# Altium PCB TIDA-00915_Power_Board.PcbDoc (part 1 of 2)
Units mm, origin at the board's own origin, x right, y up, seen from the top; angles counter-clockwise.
Board outline 80 x 46 mm, 3 copper layers (Top Layer, Signal Layer 1, Base Aluminium), stack 1.964 mm thick; 95 components, 53 nets, 450 pads, 406 vias.
Unrouted connection lines stored in the file: 2.
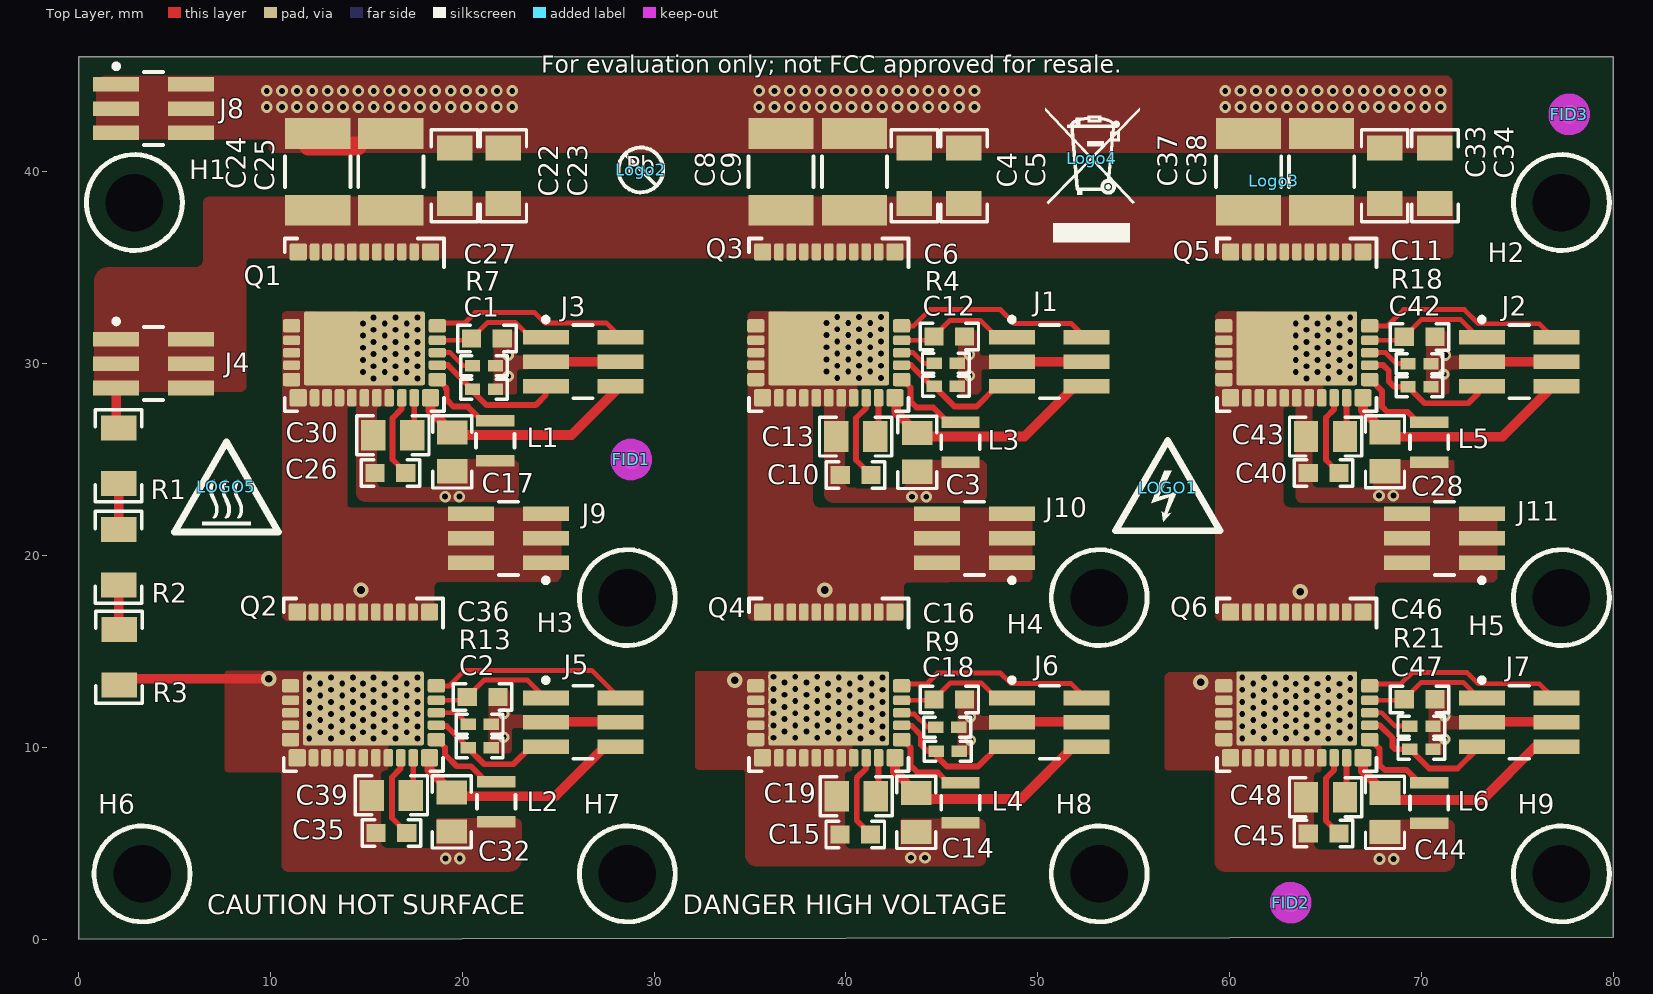
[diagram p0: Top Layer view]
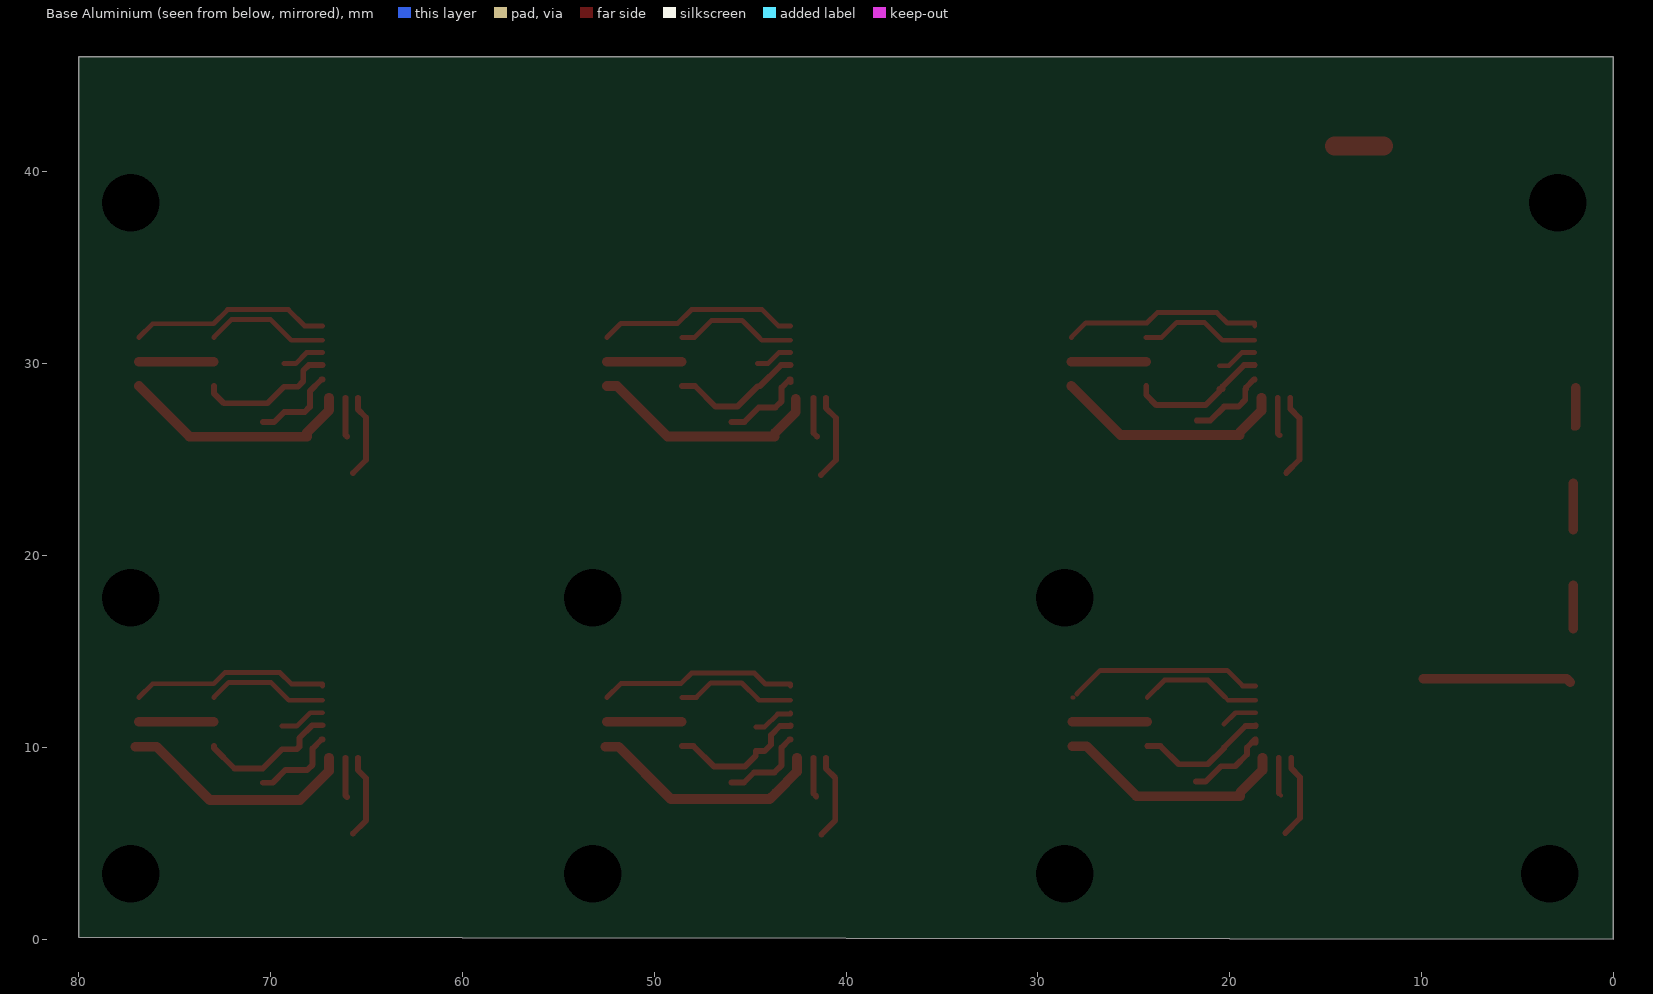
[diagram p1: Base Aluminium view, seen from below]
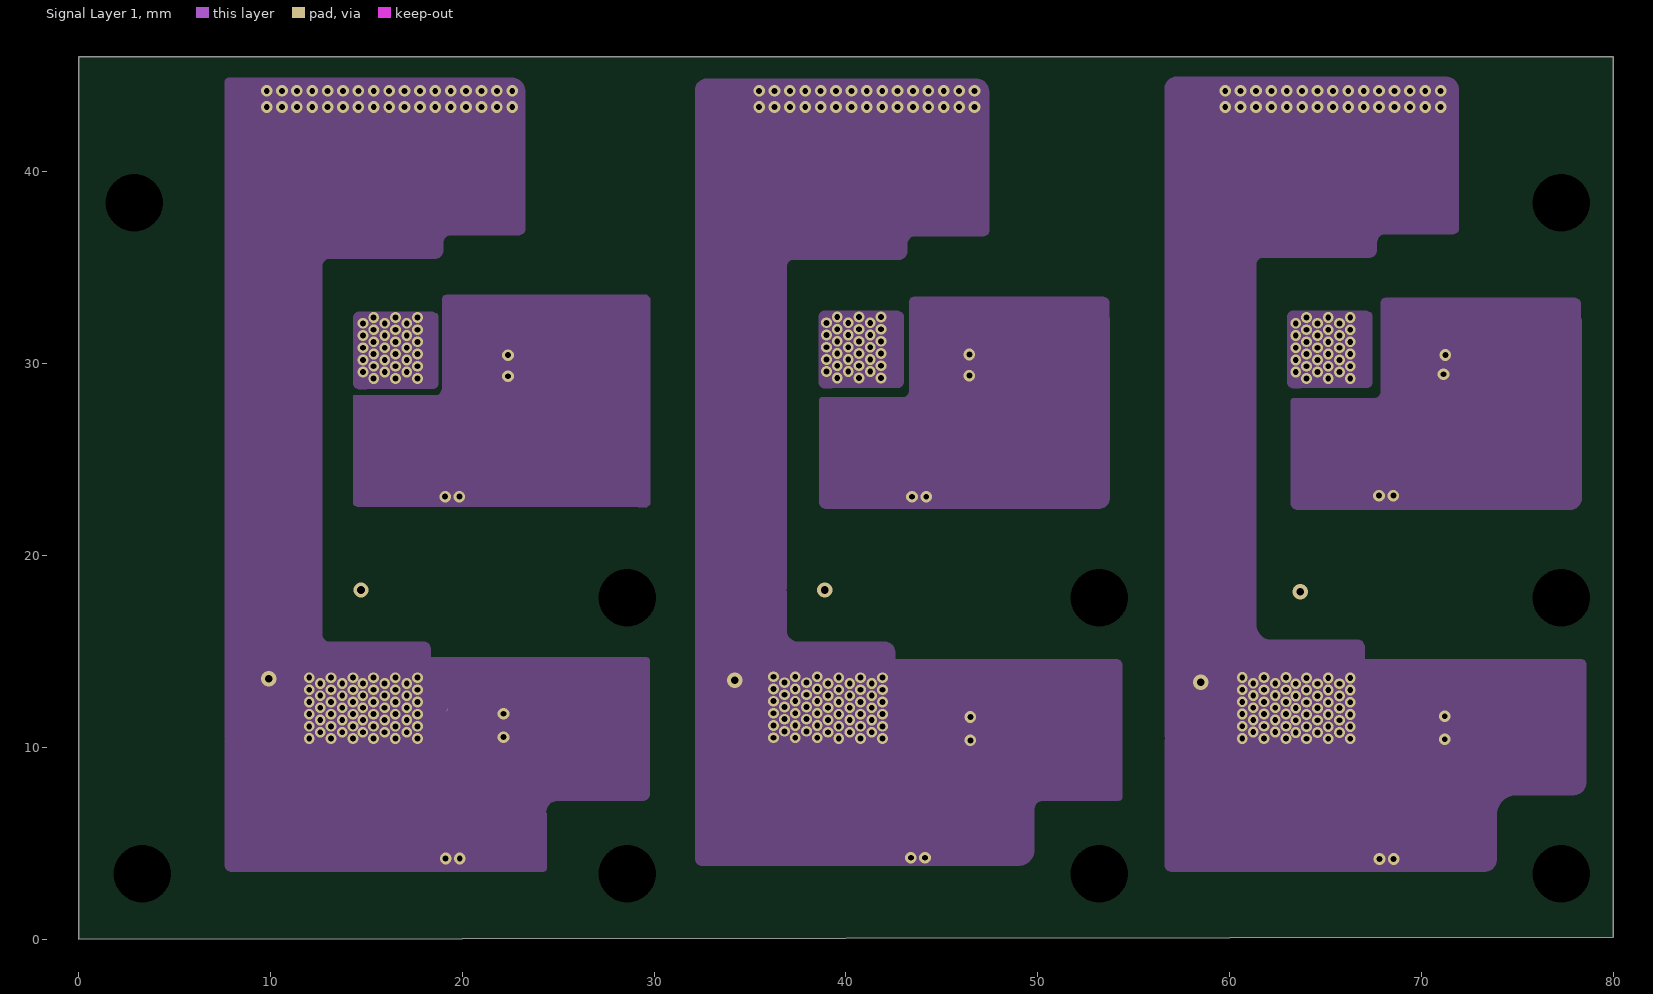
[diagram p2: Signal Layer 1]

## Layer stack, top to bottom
Top Solder: solder mask 0.0102, Solder Resist, Dk 3.5
Top Layer: signal copper 0.07
Dielectric1: dielectric 0.152, Dielectric, Dk 3.4
Signal Layer 1: signal copper 0.07
Dielectric 2: dielectric 0.152, Dk 3.4
Base Aluminium: signal copper 1.52

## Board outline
0,0 80,0.1 80,46 0,46

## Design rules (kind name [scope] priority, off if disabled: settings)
AcuteAngle [All] p1: minimum=4.50000000000000E+0001 checktracksonly=FALSE
AssemblyTestPointUsage [All] p1: valid=2
BoardOutlineClearance BoardOutlineClearance_MountingHoles [OnCopper and InComponentClass('Mounting Holes')] p1: gap=1.016 ignorepadtopadclearanceinfootprint=FALSE
BoardOutlineClearance BoardOutlineClearance_Poly [OnCopper and IsPoly] p2: gap=0.635 ignorepadtopadclearanceinfootprint=FALSE
BoardOutlineClearance [OnCopper and Not InComponentClass('Logo') and not InComponentClass('FiducialMark') and not InRegion(1000,500,4000,800) and not InPoly] p3: gap=0.5 ignorepadtopadclearanceinfootprint=FALSE
Clearance "PhaseU Sw Node" [InNetClass('PhaseU') vs NOT InNetClass('PhaseU')] p1: gap=1.6 ignorepadtopadclearanceinfootprint=TRUE
Clearance "PhaseV Sw Node" [InNetClass('PhaseV') vs NOT InNetClass('PhaseV')] p2: gap=1.6 ignorepadtopadclearanceinfootprint=FALSE
Clearance "PhaseW Sw Node" [InNetClass('PhaseW') vs NOT InNetClass('PhaseW')] p3: gap=1.6 ignorepadtopadclearanceinfootprint=FALSE except(1.524: Arc-Arc Arc-Track Track-Track)
Clearance Clearance_Keepouts [((IsTrack Or IsArc) And Not InPoly) And IsFree and IsKeepOut vs ((IsTrack Or IsArc) And Not InPoly) And IsFree and IsKeepOut] p4: gap=0 ignorepadtopadclearanceinfootprint=FALSE
Clearance Clearance_Poly [InPolygon] p5: gap=0.635 ignorepadtopadclearanceinfootprint=FALSE except(0: Arc-Hole Track-Hole SMDPad-Hole THPad-Hole Via-Hole Fill-Hole Poly-Hole Region-Hole Text-Hole; 0.254: Arc-Fill Arc-Poly Arc-Region Track-Fill Track-Poly Track-Region SMDPad-Fill SMDPad-Poly SMDPad-Region THPad-Fill THPad-Poly THPad-Region Via-Fill Via-Poly Via-Region Fill-Fill Fill-Poly Fill-Region Poly-Poly Poly-Region Region-Region)
Clearance Clearance_FiducialMark [IsKeepOut and InComponentClass('FiducialMark') vs IsPad and InComponentClass('FiducialMark')] p6: gap=0 ignorepadtopadclearanceinfootprint=FALSE
Clearance [All] p7: gap=0.254 ignorepadtopadclearanceinfootprint=TRUE except(0.203: Arc-SMDPad Track-SMDPad)
ComponentClearance ComponentClearance_MountingHoles_FiducialMarks [InComponentClass('Mounting Holes') vs InComponentClass('FiducialMark')] p1: gap=1.27 collisioncheckmode=3 verticalgap=0.254 showdistances=FALSE
ComponentClearance ComponentClearance_Shunt [InComponentClass('Header') vs InComponentClass('Shunt')] p2: gap=0 collisioncheckmode=3 verticalgap=0 showdistances=FALSE
ComponentClearance ComponentClearance_Logo [InComponentClass('Logo')] p3: gap=1.27 collisioncheckmode=3 verticalgap=0.254 showdistances=FALSE
ComponentClearance ComponentClearance_ScrewToNut [(HasFootprint('NY PMS 440 0025 PH')) vs (HasFootprint('Keystone_1902C'))] p4: gap=0.127 collisioncheckmode=3 verticalgap=0.254 showdistances=FALSE
ComponentClearance ComponentClearance_MountingHoles [InComponentClass('Mounting Holes')] p5: gap=6.35 collisioncheckmode=3 verticalgap=2540 showdistances=FALSE
ComponentClearance ComponentClearance_SmallPassives [HasFootprint('0201*') or HasFootprint('0402*') or HasFootprint('0508') or HasFootprint('0603*') or HasFootprint('0612') or HasFootprint('0805*') or HasFootprint('0815*') or HasFootprint('0830*') or HasFootprint('1206*') or HasFootprint('1210*') or HasFootprint('1808*') or HasFootprint('1812*') or HasFootprint('1825*') or HasFootprint('2010*') or HasFootprint('2220*') or HasFootprint('2225*') or HasFootprint('2512*') or HasFootprint('2728*') or HasFootprint('3518*') vs HasFootprint('0201*') or HasFootprint('0402*') or HasFootprint('0508') or HasFootprint('0603*') or HasFootprint('0612') or HasFootprint('0805*') or HasFootprint('0815*') or HasFootprint('0830*') or HasFootprint('1206*') or HasFootprint('1210*') or HasFootprint('1808*') or HasFootprint('1812*') or HasFootprint('1825*') or HasFootprint('2010*') or HasFootprint('2220*') or HasFootprint('2225*') or HasFootprint('2512*') or HasFootprint('2728*') or HasFootprint('3518*')] p6: gap=0.38 collisioncheckmode=3 verticalgap=0.254 showdistances=FALSE
ComponentClearance ComponentClearance_THtoSMT [IsThruComponent vs IsSMTComponent] p7: gap=0.5 collisioncheckmode=3 verticalgap=0.762 showdistances=FALSE
ComponentClearance ComponentClearance_THtoTH [IsThruComponent vs IsThruComponent] p8: gap=0.762 collisioncheckmode=3 verticalgap=0.762 showdistances=FALSE
ComponentClearance [All] p9: gap=0.381 collisioncheckmode=3 verticalgap=0.254 showdistances=FALSE
DiffPairsRouting [All] p1: maxlimit=2.54 minlimit=0.254 mostfreqgap=0.254 toplayer_minwidth=0.381 toplayer_maxwidth=0.381 toplayer_prefwidth=0.381 midlayer1_minwidth=0.381 midlayer1_maxwidth=0.381 midlayer1_prefwidth=0.381 bottomlayer_minwidth=0.381 bottomlayer_maxwidth=0.381 bottomlayer_prefwidth=0.381 maxuncoupledlength=25.4
FabricationTestPointUsage TestPointUsage [All] p1: valid=2 allowmultiple=FALSE
FabricationTestpoint Testpoint [All] p1: side=3 testpointundercomponent=TRUE minsize=1.016 maxsize=2.54 preferedsize=1.524 minholesize=0 maxholesize=1.016 preferedholesize=0.813 testpointgrid=0.025 allowsidetop=TRUE allowsidebottom=TRUE usegrid=TRUE gridtolerance=0
FanoutControl Fanout_LCC [IsLCC] p1: bgadir=Out bgaviamode=Centered fanoutstyle=Auto fanoutdirection=Alternating viagrid=0.025 // Fanout_LCC (Default Rule)
FanoutControl Fanout_BGA [IsBGA] p2: bgadir=Out bgaviamode=Centered fanoutstyle=Auto fanoutdirection=Alternating viagrid=0.025 // Fanout_BGA (Default Rule)
FanoutControl Fanout_Default [All] p4: bgadir=Out bgaviamode=Centered fanoutstyle=Auto fanoutdirection=Alternating viagrid=0.025 // Fanout_Default (Default Rule)
FanoutControl Fanout_Small [(CompPinCount < 5)] p5: bgadir=Out bgaviamode=Centered fanoutstyle=Auto fanoutdirection=OutThenIn viagrid=0.025 // Fanout_Small (Default Rule)
HoleSize [All] p1: absolutevalues=TRUE maxlimit=6.375 minlimit=0.2 maxpercent=80.000 minpercent=20.000
MinimumAnnularRing MinimumAnnularRing_ThermalPadVias [IsVia and InAnyComponent] p1: minimumring=0.15
MinimumAnnularRing [All] p2: minimumring=0.203
MinimumSolderMaskSliver MinimumSolderMaskSliver_Logo [InComponentClass('Logo') vs InComponentClass('Logo')] p1: minsoldermaskwidth=0.018
MinimumSolderMaskSliver [All] p2: minsoldermaskwidth=0.1
PlaneConnect [All] p1: planeconnectstyle=Direct reliefexpansion=0.254 reliefentries=4 reliefconductorwidth=0.254 reliefairgap=0.254
PolygonConnect [All] p1: connectstyle=Direct reliefconductorwidth=0.254 reliefentries=4 polygonreliefangle="90 Angle" airgapwidth=0.254
RoutingVias ThermalPadVias [IsVia and InAnyComponent] p1: holewidth=0.2 width=0.5 viastyle="Through Hole" minholewidth=0.2 minwidth=0.5 maxholewidth=0.33 maxwidth=0.6
RoutingVias [All] p2: holewidth=0.406 width=0.864 viastyle="Through Hole" minholewidth=0.2 minwidth=0.508 maxholewidth=1.016 maxwidth=1.651
SilkToBoardRegionClearance [Not ((IsComment or IsDesignator) And (Hide <> 'False')) and not InRegion(1000,500,4000,800)] p1:
SilkToSilkClearance SilkToSilkClearance_Pb-FreeLogo [(HasFootprint('Pb-Free_Overlay_Medium') OR HasFootprint('Pb-Free_Overlay_Small')) vs (HasFootprint('Pb-Free_Overlay_Medium') OR HasFootprint('Pb-Free_Overlay_Small'))] p1: silktosilkclearance=0
SilkToSilkClearance [All] p2: silktosilkclearance=0.102
SilkToSolderMaskClearance SilkToComponentPadClearance [(IsPad or IsFill or IsRegion) and InAnycomponent] p1: minsilkscreentomaskgap=0.127 clearancetoexposedcopper=TRUE
SilkToSolderMaskClearance "Silk to Solder Mask Opening" [All] p2: minsilkscreentomaskgap=0.102 clearancetoexposedcopper=FALSE
SolderMaskExpansion [All] p1: expansion=0.05
Width [All] p1: maxlimit=2.54 minlimit=0.152 preferedwidth=0.254 checkconnectedcopper=TRUE
15 further rules are at their usual default settings.

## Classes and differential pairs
net class PhaseW: 5V_H_W 12V_T_W FAULT_H_W IN_H_W NetC40_1 NetQ5_30 PHASEW SW_H_W VM12V_H_W
net class PhaseV: 5V_H_V 12V_T_V FAULT_H_V IN_H_V NetC10_1 NetQ3_30 PHASEV SW_H_V VM12V_H_V
net class PhaseU: 5V_H_U 12V_T_U FAULT_H_U IN_H_U NetC26_1 NetQ1_30 PHASEU SW_H_U VM12V_H_U
component class Header: J1 J2 J3 J4 J5 J6 J7 J8 J9 J10 J11
component class AssemblyNote: ZZ1
component class FiducialMark: FID1 FID2 FID3
component class EVM_Hardware: FID1 FID2 FID3 H1 H2 H3 H4 H5 H6 H7 H8 H9 LOGO1 Logo2 Logo3 Logo4 LOGO5 ZZ1
component class Phase_U: C1 C2 C17 C22 C23 C24 C25 C26 C27 C30 C32 C35 C36 C39 J3 J4 J5 J8 J9 L1 L2 Q1 Q2 R1 R2 R3 R7 R13
component class Phase_W: C11 C28 C33 C34 C37 C38 C40 C42 C43 C44 C45 C46 C47 C48 J2 J7 J11 L5 L6 Q5 Q6 R18 R21
component class Phase_V: C3 C4 C5 C6 C8 C9 C10 C12 C13 C14 C15 C16 C18 C19 J1 J6 J10 L3 L4 Q3 Q4 R4 R9

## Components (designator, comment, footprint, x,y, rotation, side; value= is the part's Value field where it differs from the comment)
C1 "CGA2B3X7R1E104K050BB" 0402 21.128,28.674 r0 top value=0.1uF
C2 "CGA2B3X7R1E104K050BB" 0402 20.897,9.98 r0 top value=0.1uF
C3 "C2012X7R1V475K125AC" 0805_HV 43.708,25.372 r270 top value=4.7uF
C4 "C1206X103KDRAC7800" 1206 43.565,39.8 r90 top value=0.01uF
C5 "C1206X103KDRAC7800" 1206 46.147,39.8 r90 top value=0.01uF
C6 "06035A181JAT2A" 0603 45.385,31.418 r180 top value=180pF
C8 "C1812V104KDRACTU" 1812_254 36.61,39.996 r90 top value=0.1uF
C9 "C1812V104KDRACTU" 1812_254 40.445,39.996 r90 top value=0.1uF
C10 "GCM188R71E224KA55D" 0603 40.5,24.2 r180 top value=0.22uF
C11 "06035A181JAT2A" 0603 69.9,31.4 r180 top value=180pF
C12 "CGA2B3X7R1E104K050BB" 0402 45.207,28.821 r0 top value=0.1uF
C13 "C2012X7R1V475K125AC" 0805_HV 40.5,26.2 r180 top value=4.7uF
C14 "C2012X7R1V475K125AC" 0805_HV 43.658,6.602 r270 top value=4.7uF
C15 "GCM188R71E224KA55D" 0603 40.483,5.459 r180 top value=0.22uF
C16 "06035A181JAT2A" 0603 45.385,12.495 r180 top value=180pF
C17 "C2012X7R1V475K125AC" 0805_HV 19.477,25.398 r270 top value=4.7uF
C18 "CGA2B3X7R1E104K050BB" 0402 45.309,9.803 r0 top value=0.1uF
C19 "C2012X7R1V475K125AC" 0805_HV 40.533,7.441 r180 top value=4.7uF
C22 "C1206X103KDRAC7800" 1206 19.593,39.8 r90 top value=0.01uF
C23 "C1206X103KDRAC7800" 1206 22.133,39.8 r90 top value=0.01uF
C24 "C1812V104KDRACTU" 1812_254 12.459,39.996 r90 top value=0.1uF
C25 "C1812V104KDRACTU" 1812_254 16.269,39.996 r90 top value=0.1uF
C26 "GCM188R71E224KA55D" 0603 16.251,24.306 r180 top value=0.22uF
C27 "06035A181JAT2A" 0603 21.28,31.316 r180 top value=180pF
C28 "C2012X7R1V475K125AC" 0805_HV 68.1,25.4 r270 top value=4.7uF
C30 "C2012X7R1V475K125AC" 0805_HV 16.378,26.261 r180 top value=4.7uF
C32 "C2012X7R1V475K125AC" 0805_HV 19.45,6.627 r270 top value=4.7uF
C33 "C1206X103KDRAC7800" 1206 68.084,39.8 r90 top value=0.01uF
C34 "C1206X103KDRAC7800" 1206 70.7,39.8 r90 top value=0.01uF
C35 "GCM188R71E224KA55D" 0603 16.3,5.535 r180 top value=0.22uF
C36 "06035A181JAT2A" 0603 21.05,12.622 r180 top value=180pF
C37 "C1812V104KDRACTU" 1812_254 60.988,39.996 r90 top value=0.1uF
C38 "C1812V104KDRACTU" 1812_254 64.798,39.996 r90 top value=0.1uF
C39 "C2012X7R1V475K125AC" 0805_HV 16.3,7.491 r180 top value=4.7uF
C40 "GCM188R71E224KA55D" 0603 64.9,24.3 r180 top value=0.22uF
C42 "CGA2B3X7R1E104K050BB" 0402 69.9,28.8 r0 top value=0.1uF
C43 "C2012X7R1V475K125AC" 0805_HV 65,26.2 r180 top value=4.7uF
C44 "C2012X7R1V475K125AC" 0805_HV 68.1,6.6 r270 top value=4.7uF
C45 "GCM188R71E224KA55D" 0603 64.9,5.5 r180 top value=0.22uF
C46 "06035A181JAT2A" 0603 69.9,12.5 r180 top value=180pF
C47 "CGA2B3X7R1E104K050BB" 0402 70,9.9 r0 top value=0.1uF
C48 "C2012X7R1V475K125AC" 0805_HV 65,7.4 r180 top value=4.7uF
FID1 "Fiducial" Fiducial10-20 28.8,25.004 r0 top
FID2 "Fiducial" Fiducial10-20 63.185,1.9 r0 top
FID3 "Fiducial" Fiducial10-20 77.7,43 r0 top
H1 "29331" Keystone_29331 2.9,38.4 r0 top
H2 "29331" Keystone_29331 77.3,38.4 r0 top
H3 "29331" Keystone_29331 28.6,17.8 r0 top
H4 "29331" Keystone_29331 53.2,17.8 r0 top
H5 "29331" Keystone_29331 77.3,17.8 r0 top
H6 "29331" Keystone_29331 3.3,3.4 r0 top
H7 "29331" Keystone_29331 28.6,3.4 r0 top
H8 "29331" Keystone_29331 53.2,3.4 r0 top
H9 "29331" Keystone_29331 77.3,3.4 r0 top
J1 "20021121-00006C4LF" FCI_20021121-00006x4 50.6,30.1 r0 top locked
J2 "20021121-00006C4LF" FCI_20021121-00006x4 75.1,30.1 r0 top locked
J3 "20021121-00006C4LF" FCI_20021121-00006x4 26.3,30.1 r0 top locked
J4 "20021121-00006C4LF" FCI_20021121-00006x4 3.9,30 r0 top locked
J5 "20021121-00006C4LF" FCI_20021121-00006x4 26.3,11.3 r0 top locked
J6 "20021121-00006C4LF" FCI_20021121-00006x4 50.6,11.3 r0 top locked
J7 "20021121-00006C4LF" FCI_20021121-00006x4 75.1,11.3 r0 top locked
J8 "20021121-00006C4LF" FCI_20021121-00006x4 3.9,43.3 r0 top locked
J9 "20021121-00006C4LF" FCI_20021121-00006x4 22.4,20.9 r180 top locked
J10 "20021121-00006C4LF" FCI_20021121-00006x4 46.7,20.9 r180 top locked
J11 "20021121-00006C4LF" FCI_20021121-00006x4 71.2,20.9 r180 top locked
L1 "BRC2518T220K" 1007 21.712,25.982 r90 top value=22uH
L2 "BRC2518T220K" 1007 21.761,7.161 r90 top value=22uH
L3 "BRC2518T220K" 1007 45.969,25.906 r90 top value=22uH
L4 "BRC2518T220K" 1007 45.969,7.11 r90 top value=22uH
L5 "BRC2518T220K" 1007 70.4,25.9 r90 top value=22uH
L6 "BRC2518T220K" 1007 70.4,7.1 r90 top value=22uH
LOGO1 "DANGER HIGH VOLTAGE" IEC_HighVoltage_Small 56.775,23.52 r0 top
Logo2 "Pb-Free Symbol" Pb-Free_Overlay_Small 29.3,40.1 r0 top
Logo3 "FCC disclaimer" FCC_disclaimer 62.306,39.548 r270 top
Logo4 "WEEE logo" WEEE_Minimum 52.8,40.7 r0 top
LOGO5 "CAUTION HOT SURFACE" IEC_HotSurface_Small 7.7,23.581 r0 top
Q1 "LMG3411R150RWHT" RWH0032A_NV 14.892,32.022 r270 top
Q2 "LMG3411R150RWHT" RWH0032A_NV 14.839,13.252 r270 top
Q3 "LMG3411R150RWHT" RWH0032A_NV 39.1,32.022 r270 top
Q4 "LMG3411R150RWHT" RWH0032A_NV 39.1,13.252 r270 top
Q5 "LMG3411R150RWHT" RWH0032A_NV 63.5,32.022 r270 top
Q6 "LMG3411R150RWHT" RWH0032A_NV 63.5,13.252 r270 top
R1 "CRCW1206470KJNEA" 1206 2.075,25.2 r270 top value=470k
R2 "CRCW1206470KJNEA" 1206 2.075,19.9 r270 top value=470k
R3 "CRCW1206470KJNEA" 1206 2.1,14.7 r270 top value=470k
R4 "CRCW040239K0JNED" 0402 45.207,30.015 r180 top value=39k
R7 "CRCW040239K0JNED" 0402 21.128,29.894 r180 top value=39k
R9 "CRCW040239K0JNED" 0402 45.283,11.047 r180 top value=39k
R13 "CRCW040239K0JNED" 0402 20.897,11.199 r180 top value=39k
R18 "CRCW040239K0JNED" 0402 69.9,30 r180 top value=39k
R21 "CRCW040239K0JNED" 0402 70,11.1 r180 top value=39k
ZZ1 "This Assembly Note is for PCB labels only" AssemblyNoteLabel 6.528,118.897 r0 top
ZZ2 "These assemblies are ESD sensitive, ESD precautions shall be observed." AssemblyNote 6.519,105.931 r0 top
ZZ3 "These assemblies must be clean and free from flux and all contaminants. Use of no clean flux is not acceptable." AssemblyNote 6.519,110.427 r0 top
ZZ4 "These assemblies must comply with workmanship standards IPC-A-610 Class 2, unless otherwise specified." AssemblyNote 6.519,114.922 r0 top

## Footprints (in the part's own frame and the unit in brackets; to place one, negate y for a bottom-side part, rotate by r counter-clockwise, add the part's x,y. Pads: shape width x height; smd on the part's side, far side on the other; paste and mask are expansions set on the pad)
0402 [mm] "0402 from SM-752 data"
  rect 0.8x0.6 smd: 1(-0.6,0) 2(0.6,0)
  silkscreen extent -1.22,-0.52 1.22,0.52, body extent -0.55,-0.3 0.55,0.3, height 0.6
0603 [mm] "0603 from SM-752 data"
  rect 1x0.95 smd: 1(-0.8,0) 2(0.8,0)
  silkscreen extent -1.52,-0.69 1.52,0.69, body extent -0.87,-0.47 0.87,0.47, height 1
0805_HV [mil] "0805 with 30mil clearance between pads"
  rect 50x63 smd: 1(-40,0) 2(40,0)
  silkscreen extent -74,-40 74,40, body extent -43,-29 43,29, height 57
1007 [mm] "SMD, 2-Leads, Body 2.5x1.8mm"
  rect 0.6x2 smd: 1(-1.05,0) 2(1.05,0)
  silkscreen extent -0.35,-1 0.35,1, body extent -1.35,-1 1.35,1, height 2
1206 [mm] "1206 from SM-752 data"
  rect 1.3x1.85 smd: 1(-1.45,0) 2(1.45,0)
  silkscreen extent -2.4,-1.21 2.4,1.21, body extent -1.7,-0.9 1.7,0.9, height 1.35
1812_254 [mm] "SMD, 2-Leads, Body 4.8x3.4mm"
  rect 1.6x3.4 smd: 1(-2,0) 2(2,0)
  silkscreen extent -0.8,-1.7 0.8,1.7, body extent -2.4,-1.7 2.4,1.7, height 2.54
AssemblyNote [mm] "Assembly Note"
AssemblyNoteLabel [mm] "Assembly Note for PCB Labels"
FCC_disclaimer [mm]
FCI_20021121-00006x4 [mm] "Header, 1.27mm, 3x2, SMT"
  rect 2.4x0.76 smd: 1(-1.95,1.27) 2(1.95,1.27) 3(-1.95,0) 4(1.95,0) 5(-1.95,-1.27) 6(1.95,-1.27)
  silkscreen extent -2.07,-1.9 0.5,2.32, body extent -2.75,-1.91 2.75,1.9, height 4.5
Fiducial10-20 [mm]
  round 1 smd mask+0.5: 1(0,0)
  Top Layer keep-out circle w1.178: c0,0 r0.5
IEC_HighVoltage_Small [mm]
  silkscreen extent -2.72,-2.24 2.72,2.47
IEC_HotSurface_Small [mm]
  silkscreen extent -2.72,-2.36 2.72,2.35
Keystone_29331 [mm] "M2.5 Pan Head Machine Screw"
  body extent -2.4,-2.4 2.4,2.4, height 0.26
Pb-Free_Overlay_Small [mm]
  silkscreen extent -1.16,-1.17 1.17,1.17
RWH0032A_NV [mm] "VQFN, 32-Lead, Body 8x8mm"
  rrect22% 0.9x0.9 smd paste-0.07 mask-0.05: 1(-3.8,3.45) 11(-3.8,-3.45) 17(3.8,-3.45) 27(3.8,3.45)
  rrect40% 0.9x0.5 smd paste-0.05 mask-0.05: 2(-3.8,2.6) 3(-3.8,1.95) 4(-3.8,1.3) 5(-3.8,0.65) 6(-3.8,0) 7(-3.8,-0.65) 8(-3.8,-1.3) 9(-3.8,-1.95) 10(-3.8,-2.6) 18(3.8,-2.6) 19(3.8,-1.95) 20(3.8,-1.3) 21(3.8,-0.65) 22(3.8,0) 23(3.8,0.65) 24(3.8,1.3) 25(3.8,1.95) 26(3.8,2.6)
  rrect29% 0.7x0.9 smd paste-0.05 mask-0.05: 12(0.05,-3.8) 16(2.85,-3.8) 28(2.85,3.8) 32(0.05,3.8)
  rrect40% 0.5x0.9 smd paste-0.05 mask-0.05: 13(0.8,-3.8) 14(1.45,-3.8) 15(2.1,-3.8) 29(2.1,3.8) 30(1.45,3.8) 31(0.8,3.8)
  rrect10% 1.6x0.99 on Top Paste: 33(0.314,2.38) 33(0.314,1.19) 33(0.314,0) 33(0.314,-1.19) 33(0.314,-2.38) 33(2.114,1.19) 33(2.114,2.38) 33(2.114,0) 33(2.114,-2.38) 33(2.114,-1.19)
  rrect5% 3.85x6.3 smd paste-2 mask-0.05: 33(1.225,0)
  silkscreen extent -4.5,-4.15 4.5,4.15, body extent -4,-4 4,4, height 0.9
WEEE_Minimum [mm] "WEEElie bin"
  silkscreen extent -2.42,-4.38 2.52,2.65

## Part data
C1 C2 C12 C18 C42 C47: library part CMP-0080610-1, "CAP, CERM, 0.1 µF, 25 V,+/- 10%, X7R, AEC-Q200 Grade 1, 0402", Cap_Case=0402, Manufacturer=TDK, Supplier Part Number 1=445-6902-1-ND, TempCo=X7R, Tolerance_%=10%, Value2=25V, ValueDisplayed=0.1µF
C3 C13 C14 C17 C19 C28 C30 C32 C39 C43 C44 C48: library part CMP-0007885-2, "CAP, CERM, 4.7 uF, 35 V, +/- 10%, X7R, 0805", Cap_Case=0805, Manufacturer=TDK, Supplier Part Number 1=445-7555-1-ND, TempCo=X7R, Tolerance_%=10%, Value1="0.002346 ohm", Value2=35V, ValueDisplayed=4.7uF
C4 C5 C22 C23 C33 C34: library part CMP-0085177-1, "CAP, CERM, 0.01 µF, 1000 V,+/- 10%, X7R, 1206", Cap_Case=1206, Manufacturer=Kemet, TempCo=X7R, Tolerance_%=10%, Value2=1000V, ValueDisplayed=0.01µF
C6 C11 C16 C27 C36 C46: library part CMP-0006770-4, "CAP, CERM, 180 pF, 50 V, +/- 5%, C0G/NP0, 0603", Cap_Case=0603, Manufacturer=AVX, Supplier Part Number 1=478-1178-1-ND, TempCo=C0G/NP0, Tolerance_%=5%, Value1="0.09 ohm", Value2=50V, ValueDisplayed=180pF
C8 C9 C24 C25 C37 C38: library part CMP-0009324-2, "CAP, CERM, 0.1 uF, 1000 V, +/- 10%, X7R, 1812", Cap_Case=1812, Manufacturer=Kemet, Supplier Part Number 1=399-6493-1-ND, TempCo=X7R, Tolerance_%=10%, Value1=Unknown, Value2=1000V, ValueDisplayed=0.1uF
C10 C15 C26 C35 C40 C45: library part CMP-0007140-4, "CAP, CERM, 0.22 uF, 25 V, +/- 10%, X7R, AEC-Q200 Grade 1, 0603", Cap_Case=0603, Manufacturer=MuRata, Supplier Part Number 1=490-4935-1-ND, TempCo=X7R, Tolerance_%=10%, Value1=Unknown, Value2=25V, ValueDisplayed=0.22uF
FID1 FID2 FID3: library part CMP-0077181-1, "Fiducial mark.  There is nothing to buy or mount.", Manufacturer=N/A
H1 H2 H3 H4 H5 H6 H7 H8 H9: library part CMP-0086212-3, "MACH SCREW FLAT SLOTTED #4-40", Manufacturer=Keystone
J1 J2 J3 J4 J5 J6 J7 J8 J9 J10 J11: library part CMP-0065020-2, "Header, 1.27 mm, 3x2, Au, SMT", Manufacturer=FCI, Supplier Part Number 1=609-3693-1-ND
L1 L2 L3 L4 L5 L6: library part CMP-0060002-2, "Inductor, Wirewound, 22 uH, 0.49 A, 0.56 ohm, SMD", Manufacturer="Taiyo Yuden", Supplier Part Number 1=587-2439-1-ND, Value1="0.56 ohm", Value2=0.49A, ValueDisplayed=22uH
LOGO1: library part CMP-0074835-1, "IEC 61010-1 High Voltage Warning"
Logo2: library part CMP-0074839-1
Logo3: library part CMP-0074847-1, "FCC_disclaimer"
Logo4: library part CMP-0074769-1
LOGO5: library part CMP-0074837-1, "IEC 61010-1 Hot Surface Warning"
Q1 Q2 Q3 Q4 Q5 Q6: library part CMP-0086312-1, "600-V 150mohm GaN With Integrated Driver and Cycle-by-cycle Overcurrent Protection, RWH0032A (VQFN-32), RWH0032A (VQFN-32)", Alternate Manufacturer="Texas Instruments", Alternate PartNumber=LMG3411R150RWHR
R1 R2 R3: library part CMP-0018684-3, "RES, 470 k, 5%, 0.25 W, AEC-Q200 Grade 0, 1206", Manufacturer=Vishay-Dale, Power_W=250mW, Supplier Part Number 1=541-470KECT-ND, TempCo="200 ppm/C", Tolerance_%=5%, Value2=0.25W, Value_Code=470k
R4 R7 R9 R13 R18 R21: library part CMP-0026915-3, "RES, 39 k, 5%, 0.063 W, AEC-Q200 Grade 0, 0402", Manufacturer=Vishay-Dale, Power_W=63mW, Supplier Part Number 1=541-39KJCT-ND, TempCo="200 ppm/C", Tolerance_%=5%, Value2=0.063W, Value_Code=39k0, ValueDisplayed=39k
ZZ1: library part CMP-0003616-3
ZZ2: library part CMP-0077236-1
ZZ3: library part CMP-0077237-1
ZZ4: library part CMP-0077238-1

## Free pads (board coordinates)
  round 0 hole 3 unplated: ""(2.9,38.4) ""(3.3,3.4) ""(28.6,3.4) ""(28.6,17.8) ""(53.2,3.4) ""(53.2,17.8) ""(77.3,3.4) ""(77.3,17.8) ""(77.3,38.4)

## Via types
v1: diameter 0.559, hole 0.305, Top Layer to Signal Layer 1, 282 vias
v2: diameter 0.61, hole 0.305, Top Layer to Signal Layer 1, 118 vias
v3: diameter 0.8, hole 0.4, Top Layer to Signal Layer 1, 6 vias

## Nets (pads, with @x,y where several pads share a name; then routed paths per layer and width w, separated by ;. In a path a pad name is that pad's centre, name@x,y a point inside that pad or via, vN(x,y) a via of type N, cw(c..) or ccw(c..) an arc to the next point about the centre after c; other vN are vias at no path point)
5V_H_U: C1.1 J3.5 Q1.29 | length 7.3
  Top Layer w0.305: Q1.29@18.692,29.922 19.245,29.922 20.363,28.804 20.363,28.674 C1.1@20.528,28.674 20.528,28.566 21.258,27.836 23.82,27.836 24.35,28.366 J3.5@24.35,28.83
5V_H_V: C12.1 J1.5 Q3.29 | length 7
  Top Layer w0.305: Q3.29@42.9,29.922 43.393,29.922 44.494,28.821 C12.1@44.607,28.821 44.607,28.819 45.666,27.76 46.806,27.76 47.876,28.83 J1.5@48.558,28.83
5V_H_W: C42.1 J2.5 Q5.29 | length 7.4
  Top Layer w0.305: Q5.29@67.3,29.922 68.013,29.922 68.296,29.64 68.296,29.079 68.575,28.8 C42.1@69.3,28.8 69.3,28.797 70.159,27.938 72.436,27.938 72.958,28.46 J2.5@72.958,28.83
5V_L_U: C2.1 J5.5 Q2.29 | length 6.9
  Top Layer w0.305: Q2.29@18.639,11.152 18.639,11.108 19.177,11.108 20.297,9.987 C2.1@20.297,9.98 20.297,9.952 21.133,9.116 22.657,9.116 23.6,10.06 J5.5@24.297,10.06
5V_L_V: C18.1 J6.5 Q4.29 | length 7.5
  Top Layer w0.305: Q4.29@42.9,11.152 42.9,11.108 43.438,11.108 43.914,10.631 43.914,10.13 44.241,9.803 C18.1@44.709,9.803 44.709,9.557 45.277,8.989 46.876,8.989 47.946,10.06 J6.5@48.558,10.06
5V_L_W: C47.1 J7.5 Q6.29 | length 7.4
  Top Layer w0.305: Q6.29@67.3,11.152 67.829,11.152 68.499,10.482 68.499,10.031 68.63,9.9 C47.1@69.4,9.9 69.4,9.897 70.409,8.888 71.877,8.888 72.958,9.969 J7.5@72.958,10.06
12V: C14.1 C32.1 C44.1 J5.6 J6.6 J7.6 Q2.27 Q4.27 Q6.27 | length 37.3
  Top Layer w0.508: Q2.27@18.289,9.452 18.289,8.803 C32.1@19.45,7.643 19.45,7.453 24.853,7.453 27.46,10.06 J5.6@28.197,10.06 ; Q4.27@42.55,9.452 42.55,8.726 C14.1@43.658,7.618 43.976,7.3 49.136,7.3 51.866,10.03 J6.6@52.55,10.03 ; Q6.27@66.95,9.452 66.95,8.766 C44.1@68.1,7.616 68.466,7.25 73.171,7.25 75.951,10.03 J7.6@77.05,10.03
12V_T_U: C17.1 J3.6 Q1.27 | length 12.2
  Top Layer w0.508: Q1.27@18.342,28.222 18.342,27.549 C17.1@19.477,26.414 19.477,26.275 25.695,26.275 J3.6@28.25,28.83
12V_T_V: C3.1 J1.6 Q3.27 | length 12.3
  Top Layer w0.305: Q3.27@42.55,28.222 Q3.27@42.616,28.156
  Top Layer w0.508: Q3.27@42.616,28.156 42.616,27.481 C3.1@43.708,26.388 43.708,26.199 49.301,26.199 51.933,28.83 J1.6@52.458,28.83
12V_T_W: C28.1 J2.6 Q5.27 | length 12.4
  Top Layer w0.508: Q5.27@66.95,28.222 66.95,27.566 C28.1@68.1,26.416 68.1,26.193 74.221,26.193 J2.6@76.858,28.83
FAULT_H_U: J3.2 Q1.32 | length 10.5
  Top Layer w0.254: Q1.32@18.692,31.972 18.692,32.121 20.122,32.121 20.663,32.662 23.776,32.662 24.31,32.129 27.491,32.129 J3.2@28.25,31.37
FAULT_H_V: J1.2 Q3.32 | length 10.5
  Top Layer w0.254: Q3.32@42.9,31.972 43.526,31.972 44.369,32.815 48.054,32.815 48.769,32.1 51.728,32.1 J1.2@52.458,31.37
FAULT_H_W: J2.2 Q5.32 | length 10.5
  Top Layer w0.254: Q5.32@67.3,31.972 68.23,31.972 69.073,32.815 72.239,32.815 72.973,32.08 76.148,32.08 J2.2@76.858,31.37
FAULT_L_U: J5.2 Q2.32 | length 10.2
  Top Layer w0.203: J5.2@28.147,12.6 J5.2@28.197,12.6
  Top Layer w0.254: Q2.32@18.639,13.202 19.323,13.202 20.129,14.008 26.739,14.008 J5.2@27.963,12.784
FAULT_L_V: J6.2 Q4.32 | length 10.4
  Top Layer w0.254: Q4.32@42.9,13.202 42.9,13.3 44.202,13.3 44.768,13.866 48.055,13.866 48.589,13.332 51.726,13.332 J6.2@52.458,12.6
HVBUS: C4.1 C5.1 C8.1 C9.1 C22.1 C23.1 C24.1 C25.1 C33.1 C34.1 C37.1 C38.1 J4.1 J4.2 J4.3 J4.4 J4.5 J4.6 Q1.1 Q1.2 Q1.3 Q1.4 Q1.5 Q1.6 Q1.7 Q1.8 Q1.9 Q1.10 Q1.11 Q3.1 Q3.2 Q3.3 Q3.4 Q3.5 Q3.6 Q3.7 Q3.8 Q3.9 Q3.10 Q3.11 Q5.1 Q5.2 Q5.3 Q5.4 Q5.5 Q5.6 Q5.7 Q5.8 Q5.9 Q5.10 Q5.11 R1.1 | length 2.2
  Top Layer w0.254: R1.1@1.95,26.775 ccw(c2.075,26.775) R1.1@2.075,26.65
  Top Layer w0.5: R1.1@1.95,26.775 J4.5@1.95,28.73
HVBUS_RTN: C2.2 C4.2 C5.2 C8.2 C9.2 C14.2 C15.2 C16.1 C18.2 C19.2 C22.2 C23.2 C24.2 C25.2 C32.2 C33.2 C34.2 C35.2 C36.1 C37.2 C38.2 C39.2 C44.2 C45.2 C46.1 C47.2 C48.2 J5.3 J5.4 J6.3 J6.4 J7.3 J7.4 J8.1 J8.2 J8.3 J8.4 J8.5 J8.6 L2.1 L4.1 L6.1 Q2.12 Q2.13 Q2.14 Q2.15 Q2.16 Q2.17 Q2.18 Q2.19 Q2.20 Q2.21 Q2.22 Q2.23 Q2.24 Q2.33@14.839,12.027 Q4.12 Q4.13 Q4.14 Q4.15 Q4.16 Q4.17 Q4.18 Q4.19 Q4.20 Q4.21 Q4.22 Q4.23 Q4.24 Q4.33@39.1,12.027 Q6.12 Q6.13 Q6.14 Q6.15 Q6.16 Q6.17 Q6.18 Q6.19 Q6.20 Q6.21 Q6.22 Q6.23 Q6.24 Q6.33@63.5,12.027 R3.2 R9.1 R13.1 R21.1 | length 22
  Top Layer w0.5: R3.2@2.25,13.4 2.421,13.571 v3(9.9,13.571) ; J5.3@24.297,11.33 J5.4@28.197,11.33 ; J6.3@48.558,11.33 J6.4@52.458,11.33 ; J7.3@72.958,11.33 J7.4@76.858,11.33
  Top Layer w1: C24.2@11.988,41.346 14.528,41.346
  other v1: 64.003,10.441 65.139,10.441 66.287,10.441 12.014,10.457 13.15,10.457 14.297,10.457 15.371,10.457 16.507,10.457 17.655,10.457 39.619,10.457 40.755,10.457 41.902,10.457 60.658,10.462 61.794,10.462 62.941,10.462 36.217,10.5 37.353,10.5 38.5,10.5 63.445,10.771 64.581,10.771 65.728,10.771 12.591,10.787 13.738,10.787 14.813,10.787 15.949,10.787 17.096,10.787 39.06,10.787 40.196,10.787 41.344,10.787 61.236,10.792 62.383,10.792 36.794,10.83 37.941,10.83 64.003,11.076 65.139,11.076 66.287,11.076 12.014,11.092 13.15,11.092 14.297,11.092 15.371,11.092 16.507,11.092 17.655,11.092 39.619,11.092 40.755,11.092 41.902,11.092 60.658,11.097 61.794,11.097 62.941,11.097 36.217,11.135 37.353,11.135 38.5,11.135 63.445,11.406 64.581,11.406 65.728,11.406 12.591,11.422 13.738,11.422 14.813,11.422 15.949,11.422 17.096,11.422 39.06,11.422 40.196,11.422 41.344,11.422 61.236,11.427 62.383,11.427 36.794,11.465 37.941,11.465 64.003,11.711 65.139,11.711 66.287,11.711 12.014,11.727 13.15,11.727 14.297,11.727 15.371,11.727 16.507,11.727 17.655,11.727 39.619,11.727 40.755,11.727 41.902,11.727 60.658,11.732 61.794,11.732 62.941,11.732 36.217,11.77 37.353,11.77 38.5,11.77 63.445,12.041 64.581,12.041 65.728,12.041 12.591,12.057 13.738,12.057 14.813,12.057 15.949,12.057 17.096,12.057 39.06,12.057 40.196,12.057 41.344,12.057 61.236,12.062 62.383,12.062 36.794,12.1 37.941,12.1 64.003,12.346 65.139,12.346 66.287,12.346 12.014,12.362 13.15,12.362 14.297,12.362 15.371,12.362 16.507,12.362 17.655,12.362 39.619,12.362 40.755,12.362 41.902,12.362 60.658,12.367 61.794,12.367 62.941,12.367 36.217,12.405 37.353,12.405 38.5,12.405 63.445,12.676 64.581,12.676 65.728,12.676 12.591,12.692 13.738,12.692 14.813,12.692 15.949,12.692 17.096,12.692 39.06,12.692 40.196,12.692 41.344,12.692 61.236,12.697 62.383,12.697 36.794,12.735 37.941,12.735 64.003,12.981 65.139,12.981 66.287,12.981 12.014,12.997 13.15,12.997 14.297,12.997 15.371,12.997 16.507,12.997 17.655,12.997 39.619,12.997 40.755,12.997 41.902,12.997 60.658,13.002 61.794,13.002 62.941,13.002 36.217,13.04 37.353,13.04 38.5,13.04 63.445,13.311 64.581,13.311 65.728,13.311 12.591,13.327 13.738,13.327 14.813,13.327 15.949,13.327 17.096,13.327 39.06,13.327 40.196,13.327 41.344,13.327 61.236,13.332 62.383,13.332 36.794,13.37 37.941,13.37 64.003,13.616 65.139,13.616 66.287,13.616 12.014,13.632 13.15,13.632 14.297,13.632 15.371,13.632 16.507,13.632 17.655,13.632 39.619,13.632 40.755,13.632 41.902,13.632 60.658,13.637 61.794,13.637 62.941,13.637 36.217,13.675 37.353,13.675 38.5,13.675
  other v2: 67.815,4.174 68.55,4.174 19.126,4.2 19.86,4.2 43.381,4.24 44.115,4.24 46.483,10.362 71.219,10.421 22.147,10.53 46.483,11.581 71.219,11.621 22.147,11.749 9.798,43.384 10.6,43.384 11.369,43.384 12.172,43.384 12.974,43.384 13.776,43.384 14.578,43.384 15.38,43.384 16.183,43.384 16.985,43.384 17.787,43.384 18.589,43.384 19.391,43.384 20.193,43.384 20.996,43.384 21.798,43.384 22.6,43.384 35.469,43.384 36.272,43.384 37.074,43.384 37.876,43.384 38.678,43.384 39.48,43.384 40.283,43.384 41.085,43.384 41.887,43.384 42.689,43.384 43.491,43.384 44.293,43.384 45.096,43.384 45.898,43.384 46.7,43.384 59.769,43.384 60.572,43.384 61.374,43.384 62.176,43.384 62.978,43.384 63.78,43.384 64.583,43.384 65.385,43.384 66.187,43.384 66.989,43.384 67.791,43.384 68.593,43.384 69.396,43.384 70.198,43.384 71,43.384 9.798,44.222 10.6,44.222 11.369,44.222 12.172,44.222 12.974,44.222 13.776,44.222 14.578,44.222 15.38,44.222 16.183,44.222 16.985,44.222 17.787,44.222 18.589,44.222 19.391,44.222 20.193,44.222 20.996,44.222 21.798,44.222 22.6,44.222 35.469,44.222 36.272,44.222 37.074,44.222 37.876,44.222 38.678,44.222 39.48,44.222 40.283,44.222 41.085,44.222 41.887,44.222 42.689,44.222 43.491,44.222 44.293,44.222 45.096,44.222 45.898,44.222 46.7,44.222 59.769,44.222 60.572,44.222 61.374,44.222 62.176,44.222 62.978,44.222 63.78,44.222 64.583,44.222 65.385,44.222 66.187,44.222 66.989,44.222 67.791,44.222 68.593,44.222 69.396,44.222 70.198,44.222 71,44.222
  other v3: 58.5,13.384 34.2,13.5
IN_H_U: C27.2 J3.1 Q1.31 | length 6.4
  Top Layer w0.254: Q1.31@18.692,31.222 20.386,31.222 C27.2@20.48,31.316 21.318,32.154 22.758,32.154 23.542,31.37 J3.1@24.35,31.37
IN_H_V: C6.2 J1.1 Q3.31 | length 6.5
  Top Layer w0.254: Q3.31@42.9,31.222 44.389,31.222 C6.2@44.585,31.418 45.423,32.256 47.004,32.256 47.89,31.37 J1.1@48.558,31.37
IN_H_W: C11.2 J2.1 Q5.31 | length 6.5
  Top Layer w0.254: Q5.31@67.3,31.222 68.922,31.222 C11.2@69.1,31.4 70.007,32.307 72.029,32.307 72.958,31.377 J2.1@72.958,31.37
IN_L_U: C36.2 J5.1 Q2.31 | length 6.5
  Top Layer w0.2: C36.2@20.08,12.452 C36.2@20.25,12.622
  Top Layer w0.254: Q2.31@18.639,12.452 C36.2@20.08,12.452 ; C36.2@20.25,12.622 21.128,13.5 23.397,13.5 J5.1@24.297,12.6
IN_L_V: C16.2 J6.1 Q4.31 | length 6.3
  Top Layer w0.254: Q4.31@42.9,12.452 44.542,12.452 C16.2@44.585,12.495 45.448,13.358 47.042,13.358 47.801,12.6 J6.1@48.558,12.6
IN_L_W: C46.2 J7.1 Q6.31 | length 6.4
  Top Layer w0.254: Q6.31@67.3,12.452 69.052,12.452 C46.2@69.1,12.5 69.984,13.384 72.174,13.384 J7.1@72.958,12.6
NetC10_1: C10.1 Q3.25 | length 4.6
  Top Layer w0.305: Q3.25@41.05,28.222 41.05,27.692 40.525,27.168 40.525,24.975 C10.1@41.3,24.2
NetC15_1: C15.1 Q4.25 | length 4.5
  Top Layer w0.305: Q4.25@41.05,9.452 41.05,8.896 40.559,8.405 40.559,6.183 C15.1@41.283,5.459
NetC26_1: C26.1 Q1.25 | length 4.4
  Top Layer w0.305: Q1.25@16.842,28.222 16.842,27.647 16.353,27.158 16.353,25.004 C26.1@17.051,24.306
NetC35_1: C35.1 Q2.25 | length 4.4
  Top Layer w0.305: Q2.25@16.789,9.452 16.789,8.902 16.325,8.438 16.325,6.31 C35.1@17.1,5.535
NetC40_1: C40.1 Q5.25 | length 4.4
  Top Layer w0.305: Q5.25@65.45,28.222 65.45,27.622 65.025,27.198 65.025,24.975 C40.1@65.7,24.3
NetC45_1: C45.1 Q6.25 | length 4.4
  Top Layer w0.305: Q6.25@65.45,9.452 65.45,8.811 65.025,8.386 65.025,6.175 C45.1@65.7,5.5
NetJ7_2: J7.2 Q6.32 | length 10.4
  Top Layer w0.254: Q6.32@67.3,13.202 67.3,13.305 68.921,13.305 69.508,13.892 72.385,13.892 72.966,13.31 76.148,13.31 J7.2@76.858,12.6
NetQ1_30: Q1.30 R7.2 | length 2.1
  Top Layer w0.254: Q1.30@18.692,30.572 19.357,30.572 20.036,29.894 R7.2@20.528,29.894
NetQ2_30: Q2.30 R13.2 | length 1.9
  Top Layer w0.254: Q2.30@18.639,11.802 19.695,11.802 R13.2@20.297,11.199
NetQ3_30: Q3.30 R4.2 | length 1.9
  Top Layer w0.254: Q3.30@42.9,30.572 43.498,30.572 44.054,30.015 R4.2@44.607,30.015
NetQ4_30: Q4.30 R9.2 | length 2.1
  Top Layer w0.254: Q4.30@42.9,11.802 42.9,11.732 43.568,11.732 44.252,11.047 R9.2@44.683,11.047
NetQ5_30: Q5.30 R18.2 | length 2.2
  Top Layer w0.254: Q5.30@67.3,30.572 68.125,30.572 68.697,30 R18.2@69.3,30
NetQ6_30: Q6.30 R21.2 | length 2.4
  Top Layer w0.254: Q6.30@67.3,11.802 67.933,11.802 68.635,11.1 R21.2@69.4,11.1
NetR1_2: R1.2 R2.1 | length 2.4
  Top Layer w0.5: R2.1@2.075,21.35 R1.2@2.075,23.75
NetR2_2: R2.2 R3.1 | length 2.3
  Top Layer w0.254: R3.1@2.075,16.175 ccw(c2.1,16.175) R3.1@2.1,16.15
  Top Layer w0.5: R3.1@2.075,16.175 R2.2@2.075,18.45
PHASEU: C1.2 C17.2 C26.2 C27.1 C30.2 J3.3 J3.4 J9.1 J9.2 J9.3 J9.4 J9.5 J9.6 L1.1 Q1.12 Q1.13 Q1.14 Q1.15 Q1.16 Q1.17 Q1.18 Q1.19 Q1.20 Q1.21 Q1.22 Q1.23 Q1.24 Q1.33@14.892,30.797 Q2.1 Q2.2 Q2.3 Q2.4 Q2.5 Q2.6 Q2.7 Q2.8 Q2.9 Q2.10 Q2.11 R7.1 | length 3.9
  Top Layer w0.5: J3.3@24.35,30.1 J3.4@28.25,30.1
  other v1: 15.373,29.23 16.509,29.23 17.656,29.23 14.814,29.56 15.95,29.56 17.097,29.56 15.373,29.865 16.509,29.865 17.656,29.865 14.814,30.195 15.95,30.195 17.097,30.195 15.373,30.5 16.509,30.5 17.656,30.5 14.814,30.83 15.95,30.83 17.097,30.83 15.373,31.135 16.509,31.135 17.656,31.135 14.814,31.465 15.95,31.465 17.097,31.465 15.373,31.77 16.509,31.77 17.656,31.77 14.814,32.1 15.95,32.1 17.097,32.1 15.373,32.405 16.509,32.405 17.656,32.405
  other v2: 19.1,23.068 19.845,23.068 22.378,29.344 22.378,30.444
  other v3: 14.713,18.2
PHASEV: C3.2 C6.1 C10.2 C12.2 C13.2 J1.3 J1.4 J10.1 J10.2 J10.3 J10.4 J10.5 J10.6 L3.1 Q3.12 Q3.13 Q3.14 Q3.15 Q3.16 Q3.17 Q3.18 Q3.19 Q3.20 Q3.21 Q3.22 Q3.23 Q3.24 Q3.33@39.1,30.797 Q4.1 Q4.2 Q4.3 Q4.4 Q4.5 Q4.6 Q4.7 Q4.8 Q4.9 Q4.10 Q4.11 R4.1 | length 3.9
  Top Layer w0.5: J1.3@48.558,30.1 J1.4@52.458,30.1
  other v1: 39.54,29.257 40.676,29.257 41.823,29.257 38.981,29.587 40.117,29.587 41.264,29.587 39.54,29.892 40.676,29.892 41.823,29.892 38.981,30.222 40.117,30.222 41.264,30.222 39.54,30.527 40.676,30.527 41.823,30.527 38.981,30.857 40.117,30.857 41.264,30.857 39.54,31.162 40.676,31.162 41.823,31.162 38.981,31.492 40.117,31.492 41.264,31.492 39.54,31.797 40.676,31.797 41.823,31.797 38.981,32.127 40.117,32.127 41.264,32.127 39.54,32.432 40.676,32.432 41.823,32.432
  other v2: 43.438,23.061 44.182,23.061 46.432,29.377 46.432,30.477
  other v3: 38.9,18.2
PHASEW: C11.1 C28.2 C40.2 C42.2 C43.2 J2.3 J2.4 J11.1 J11.2 J11.3 J11.4 J11.5 J11.6 L5.1 Q5.12 Q5.13 Q5.14 Q5.15 Q5.16 Q5.17 Q5.18 Q5.19 Q5.20 Q5.21 Q5.22 Q5.23 Q5.24 Q5.33@63.5,30.797 Q6.1 Q6.2 Q6.3 Q6.4 Q6.5 Q6.6 Q6.7 Q6.8 Q6.9 Q6.10 Q6.11 R18.1 | length 3.9
  Top Layer w0.5: J2.3@72.958,30.1 J2.4@76.858,30.1
  other v1: 64.003,29.23 65.139,29.23 66.286,29.23 63.444,29.56 64.58,29.56 65.727,29.56 64.003,29.865 65.139,29.865 66.286,29.865 63.444,30.195 64.58,30.195 65.727,30.195 64.003,30.5 65.139,30.5 66.286,30.5 63.444,30.83 64.58,30.83 65.727,30.83 64.003,31.135 65.139,31.135 66.286,31.135 63.444,31.465 64.58,31.465 65.727,31.465 64.003,31.77 65.139,31.77 66.286,31.77 63.444,32.1 64.58,32.1 65.727,32.1 64.003,32.405 65.139,32.405 66.286,32.405
  other v2: 67.792,23.119 68.536,23.119 71.15,29.45 71.248,30.452
  other v3: 63.689,18.1
SW_H_U: L1.2 Q1.28 | length 4.3
  Top Layer w0.305: Q1.28@18.692,29.172 18.737,29.172 19.148,28.761 19.148,28.683 19.181,28.683 19.181,28.114 19.535,27.76 20.284,27.76 21.012,27.032 L1.2@21.712,27.032
SW_H_V: L3.2 Q3.28 | length 4.6
  Top Layer w0.305: Q3.28@42.9,29.028 Q3.28@42.9,29.172 42.945,29.172 43.356,28.761 43.356,28.036 43.683,27.709 44.547,27.709 45.3,26.956 L3.2@45.969,26.956
SW_H_W: L5.2 Q5.28 | length 4.5
  Top Layer w0.305: Q5.28@67.3,29.172 67.345,29.172 67.953,28.564 67.953,27.747 68.219,27.481 69.286,27.481 69.817,26.95 L5.2@70.4,26.95
SW_L_U: L2.2 Q2.28 | length 4.6
  Top Layer w0.3: Q2.28@18.639,10.402 18.639,10.255 Q2.28@18.828,10.255
  Top Layer w0.305: Q2.28@18.639,10.402 18.684,10.402 19.095,9.991 19.095,9.624 19.705,9.015 20.445,9.015 21.249,8.211 L2.2@21.761,8.211
SW_L_V: L4.2 Q4.28 | length 4.5
  Top Layer w0.305: Q4.28@42.9,10.402 42.945,10.402 43.356,9.991 43.356,9.066 43.737,8.685 44.791,8.685 45.315,8.16 L4.2@45.969,8.16
SW_L_W: L6.2 Q6.28 | length 4.5
  Top Layer w0.305: Q6.28@67.3,10.402 67.345,10.402 67.808,9.939 67.808,9.096 68.093,8.811 69.228,8.811 69.889,8.15 L6.2@70.4,8.15
VM12V_H_U: C30.1 Q1.26 | length 2
  Top Layer w0.3: C30.1@17.394,26.261 C30.1@17.492,26.359
  Top Layer w0.305: C30.1@17.492,26.359 Q1.26@17.492,28.222
VM12V_H_V: C13.1 Q3.26 | length 2.1
  Top Layer w0.3: C13.1@41.516,26.2 C13.1@41.7,26.384
  Top Layer w0.305: C13.1@41.7,26.384 Q3.26@41.7,28.222
VM12V_H_W: C43.1 Q5.26 | length 2.1
  Top Layer w0.305: C43.1@66.016,26.2 66.1,26.284 Q5.26@66.1,28.222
